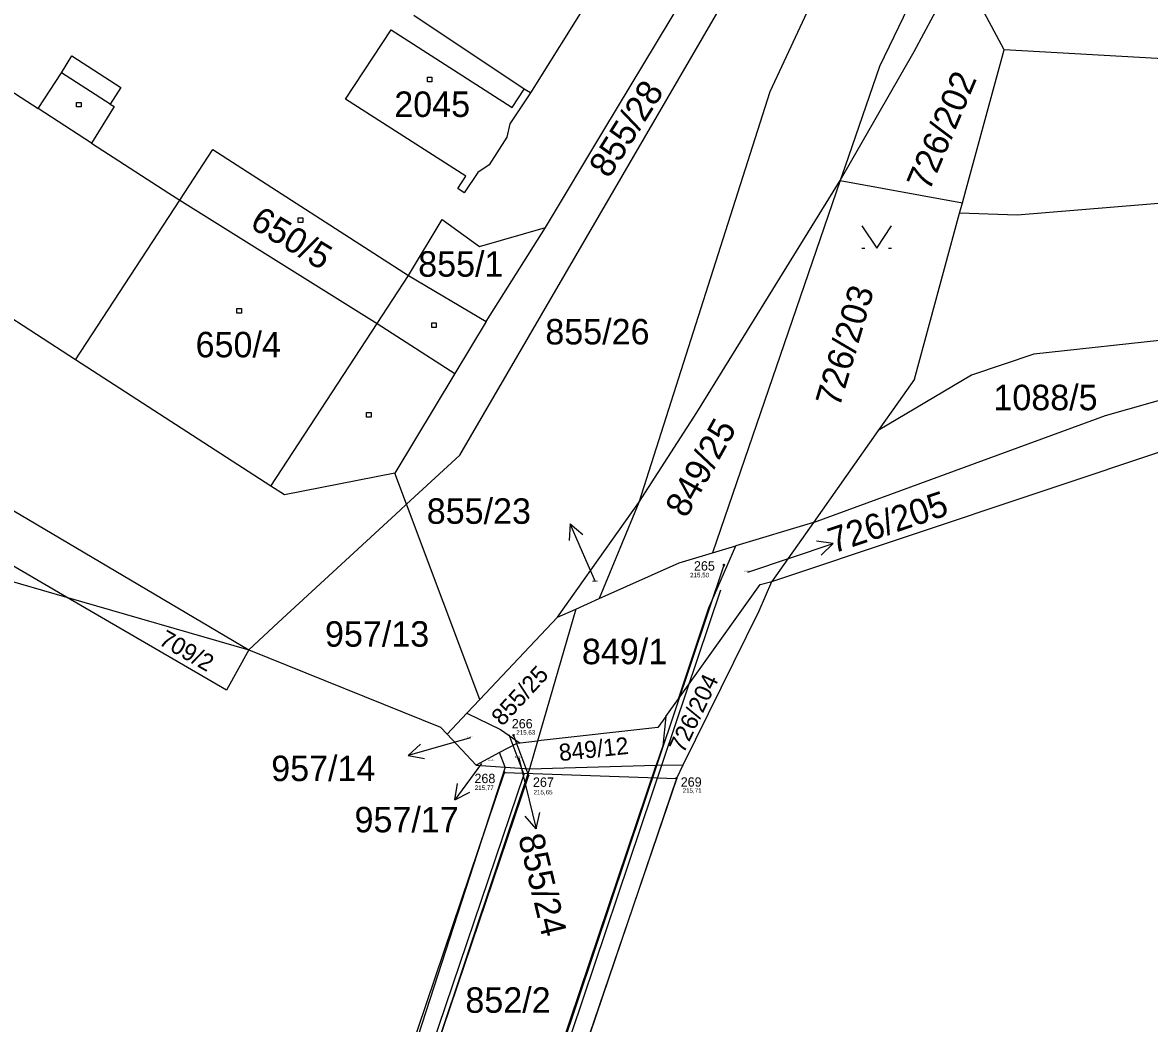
# Model space of a CAD drawing. Extents: x -711879 to -711361, y -1048782 to -1048177.
# Drawn here: x -711646.6 to -711571.3, y -1048438.5 to -1048371.7 of the extents above; entities that cross this region are included whole.
import ezdxf

# ---------------------------------------------------------------- set-up
doc = ezdxf.new("R2010")
doc.units = 0
for name, color, linetype in [('body', 7, 'Continuous'), ('kresba', 7, 'Continuous'), ('Vrstva 1', 7, 'Continuous'), ('Vrstva 13', 7, 'Continuous'), ('Vrstva 14', 7, 'Continuous'), ('Vrstva 15', 7, 'Continuous'), ('Vrstva 16', 7, 'Continuous'), ('Vrstva 2', 7, 'Continuous'), ('Vrstva 20', 7, 'Continuous'), ('Vrstva 23', 7, 'Continuous'), ('Vrstva 25', 7, 'Continuous'), ('Vrstva 41', 7, 'Continuous'), ('Vrstva 46', 7, 'Continuous'), ('výšky', 7, 'Continuous')]:
    doc.layers.add(name, color=color, linetype=linetype)

msp = doc.modelspace()

# ---------------------------------------------------------------- linework, layer by layer
at = {"layer": 'kresba'}
msp.add_line((-711599.74, -1048407.86), (-711614.77, -1048452.56), dxfattribs=at)
for points in [[(-711630.48, -1048500.11), (-711629, -1048495.83), (-711614.47, -1048452.67), (-711599.94, -1048409.51)], [(-711614.09, -1048419.16), (-711613.1, -1048421.84), (-711622.61, -1048449.96)], [(-711613.78, -1048419.23), (-711612.79, -1048421.91), (-711622.3, -1048450.03)]]:
    msp.add_lwpolyline(points, dxfattribs=at)
msp.add_lwpolyline([(-711614.39, -1048421.71), (-711602.91, -1048422.1), (-711612.41, -1048450.08), (-711623.65, -1048449.1)], close=True, dxfattribs=at)
at = {"layer": 'Vrstva 1'}
for p, q in [((-711598.7, -1048354.08), (-711612.66, -1048376.35)), ((-711607.76, -1048378.85), (-711593.27, -1048354.78)), ((-711678.36, -1048356.19), (-711645.51, -1048377.4)), ((-711590.17, -1048362.3), (-711596.67, -1048376.28)), ((-711583.43, -1048362.34), (-711589.37, -1048374.59)), ((-711617.37, -1048400.54), (-711595.83, -1048363.49)), ((-711643.01, -1048394.17), (-711685.27, -1048366.88)), ((-711587.04, -1048373.59), (-711584.04, -1048367.95)), ((-711613.07, -1048376.1), (-711620.44, -1048371.18)), ((-711581.05, -1048373.49), (-711582.56, -1048370.66)), ((-711624.99, -1048376.78), (-711621.96, -1048372.14)), ((-711621.96, -1048372.14), (-711613.87, -1048377.34)), ((-711583.58, -1048382.77), (-711581.05, -1048373.49)), ((-711557.26, -1048374.8), (-711581.05, -1048373.49)), ((-711643.94, -1048375.01), (-711643.26, -1048373.89)), ((-711643.26, -1048373.89), (-711639.98, -1048376)), ((-711591.98, -1048382.19), (-711587.04, -1048373.59)), ((-711589.37, -1048374.59), (-711591.65, -1048381.24)), ((-711645.51, -1048377.4), (-711643.94, -1048375.01)), ((-711639.98, -1048376), (-711640.7, -1048377.1)), ((-711612.66, -1048376.35), (-711614.03, -1048378.43)), ((-711613.87, -1048377.34), (-711613.07, -1048376.1)), ((-711612.66, -1048376.35), (-711613.07, -1048376.1)), ((-711596.67, -1048376.28), (-711605.43, -1048403.69)), ((-711640.7, -1048377.1), (-711640.43, -1048377.27)), ((-711616.96, -1048381.91), (-711624.99, -1048376.78)), ((-711640.43, -1048377.27), (-711641.94, -1048379.7)), ((-711614.03, -1048378.43), (-711614.22, -1048379.32)), ((-711502.66, -1048378.02), (-711580.18, -1048384.52)), ((-711614.22, -1048379.32), (-711615.41, -1048381.15)), ((-711611.66, -1048385.34), (-711607.76, -1048378.85)), ((-711641.94, -1048379.7), (-711636.78, -1048383.04)), ((-711636.05, -1048383.51), (-711633.84, -1048380.13)), ((-711633.84, -1048380.13), (-711620.8, -1048388.55)), ((-711616.17, -1048381.67), (-711617.07, -1048383.03)), ((-711615.41, -1048381.15), (-711616.17, -1048381.67)), ((-711591.65, -1048381.24), (-711591.98, -1048382.19)), ((-711617.49, -1048382.73), (-711616.96, -1048381.91)), ((-711601.56, -1048397.68), (-711591.98, -1048382.19)), ((-711591.98, -1048382.19), (-711600.51, -1048407.04)), ((-711591.98, -1048382.19), (-711583.83, -1048383.69)), ((-711636.78, -1048383.04), (-711636.05, -1048383.51)), ((-711617.07, -1048383.03), (-711617.49, -1048382.73)), ((-711583.83, -1048383.69), (-711583.58, -1048382.77)), ((-711643.01, -1048394.17), (-711636.05, -1048383.51)), ((-711636.05, -1048383.51), (-711622.88, -1048391.74)), ((-711584.02, -1048384.39), (-711583.83, -1048383.69)), ((-711587.03, -1048395.45), (-711584.02, -1048384.39)), ((-711580.18, -1048384.52), (-711584.02, -1048384.39)), ((-711620.8, -1048388.55), (-711618.55, -1048384.81)), ((-711618.55, -1048384.81), (-711616.05, -1048386.61)), ((-711616.05, -1048386.61), (-711611.66, -1048385.34)), ((-711615.61, -1048391.61), (-711611.66, -1048385.34)), ((-711620.8, -1048388.55), (-711615.61, -1048391.61)), ((-711548.59, -1048390.49), (-711579.07, -1048393.79)), ((-711574.28, -1048397.89), (-711548.59, -1048390.49)), ((-711596.54, -1048408.95), (-711544.38, -1048391.51)), ((-711622.88, -1048391.74), (-711617.7, -1048395.07)), ((-711615.61, -1048391.61), (-711617.7, -1048395.07)), ((-711579.07, -1048393.79), (-711583.23, -1048395.19)), ((-711629.97, -1048402.59), (-711643.01, -1048394.17)), ((-711617.7, -1048395.07), (-711621.7, -1048401.73)), ((-711583.23, -1048395.19), (-711589.45, -1048398.89)), ((-711587.03, -1048395.45), (-711588.09, -1048396.96)), ((-711588.09, -1048396.96), (-711589.45, -1048398.89)), ((-711605.43, -1048403.69), (-711601.56, -1048397.68)), ((-711593.77, -1048405.02), (-711574.28, -1048397.89)), ((-711589.45, -1048398.89), (-711593.77, -1048405.02)), ((-711620.92, -1048403.81), (-711617.37, -1048400.54)), ((-711653.14, -1048400.7), (-711631.45, -1048413.51)), ((-711621.7, -1048401.73), (-711629.06, -1048403.18)), ((-711620.92, -1048403.81), (-711621.7, -1048401.73)), ((-711629.06, -1048403.18), (-711629.97, -1048402.59)), ((-711664.88, -1048403.87), (-711643.62, -1048410)), ((-711629.49, -1048411.7), (-711621.36, -1048404.21)), ((-711621.36, -1048404.21), (-711620.92, -1048403.81)), ((-711616.04, -1048416.84), (-711620.92, -1048403.81)), ((-711610.85, -1048411.35), (-711605.43, -1048403.69)), ((-711605.43, -1048403.69), (-711608.06, -1048410.1)), ((-711643.62, -1048410), (-711653.11, -1048404.49)), ((-711593.77, -1048405.02), (-711598.96, -1048406.58)), ((-711593.77, -1048405.02), (-711596.54, -1048408.95)), ((-711600.51, -1048407.04), (-711598.96, -1048406.58)), ((-711602.74, -1048407.71), (-711600.51, -1048407.04)), ((-711608.06, -1048410.1), (-711602.74, -1048407.71)), ((-711602.78, -1048416.79), (-711597.32, -1048409.17)), ((-711597.39, -1048410.92), (-711596.54, -1048408.95)), ((-711597.32, -1048409.17), (-711596.54, -1048408.95)), ((-711643.62, -1048410), (-711631.45, -1048413.51)), ((-711632.93, -1048416.21), (-711643.62, -1048410)), ((-711609.62, -1048410.8), (-711608.06, -1048410.1)), ((-711609.62, -1048410.8), (-711612.18, -1048419.61)), ((-711610.85, -1048411.35), (-711609.62, -1048410.8)), ((-711602.46, -1048421.2), (-711597.39, -1048410.92)), ((-711629.49, -1048411.7), (-711631.45, -1048413.51)), ((-711616.04, -1048416.84), (-711610.85, -1048411.35)), ((-711631.45, -1048413.51), (-711632.93, -1048416.21)), ((-711631.45, -1048413.51), (-711618.65, -1048418.68)), ((-711616.9, -1048417.75), (-711616.04, -1048416.84)), ((-711603.62, -1048417.96), (-711602.78, -1048416.79)), ((-711618.22, -1048419.15), (-711616.9, -1048417.75)), ((-711603.62, -1048417.96), (-711604.15, -1048418.71)), ((-711603.62, -1048417.96), (-711603.83, -1048419.93)), ((-711618.65, -1048418.68), (-711618.22, -1048419.15)), ((-711618.22, -1048419.15), (-711616.27, -1048421.22)), ((-711604.15, -1048418.71), (-711611.95, -1048419.58)), ((-711613.57, -1048419.77), (-711614.71, -1048420.38)), ((-711613.34, -1048419.74), (-711613.57, -1048419.77)), ((-711612.18, -1048419.61), (-711613.34, -1048419.74)), ((-711612.18, -1048419.61), (-711612.72, -1048421.45)), ((-711611.95, -1048419.58), (-711612.18, -1048419.61)), ((-711603.83, -1048419.93), (-711604.27, -1048421.22)), ((-711614.71, -1048420.38), (-711616.27, -1048421.22)), ((-711614.35, -1048421.34), (-711614.71, -1048420.38)), ((-711614.35, -1048421.34), (-711623.23, -1048448.72)), ((-711616.27, -1048421.22), (-711614.35, -1048421.34)), ((-711614.35, -1048421.34), (-711612.72, -1048421.45)), ((-711612.72, -1048421.45), (-711604.27, -1048421.22)), ((-711604.27, -1048421.22), (-711602.46, -1048421.2)), ((-711602.89, -1048422.08), (-711602.46, -1048421.2)), ((-711602.89, -1048422.08), (-711615.16, -1048458.11))]:
    msp.add_line(p, q, dxfattribs=at)
for points in [[(-711602.78, -1048416.79), (-711600.74, -1048410.71), (-711598.96, -1048406.58)], [(-711616.9, -1048417.75), (-711614.65, -1048418.83), (-711613.34, -1048419.74)]]:
    msp.add_lwpolyline(points, dxfattribs=at)
at = {"layer": 'Vrstva 13'}
for p, q in [((-711608.31, -1048408.99), (-711608.81, -1048407.86)), ((-711598.14, -1048408.33), (-711595.3, -1048407.37)), ((-711616.65, -1048419.39), (-711617.93, -1048419.75)), ((-711613.44, -1048420.73), (-711612.99, -1048422.55))]:
    msp.add_line(p, q, dxfattribs=at)
at = {"layer": 'Vrstva 16'}
for p, q in [((-711610.013, -1048405.112), (-711610.07, -1048406.228)), ((-711608.81, -1048407.86), (-711610.013, -1048405.112)), ((-711610.013, -1048405.112), (-711609.154, -1048405.827)), ((-711595.3, -1048407.37), (-711592.456, -1048406.413)), ((-711592.456, -1048406.413), (-711593.563, -1048406.258)), ((-711592.456, -1048406.413), (-711593.244, -1048407.206)), ((-711617.93, -1048419.75), (-711620.814, -1048420.575)), ((-711620.814, -1048420.575), (-711619.99, -1048419.819)), ((-711620.814, -1048420.575), (-711619.715, -1048420.78)), ((-711615.931, -1048421.113), (-711617.703, -1048423.533)), ((-711617.703, -1048423.533), (-711617.516, -1048422.431)), ((-711617.703, -1048423.533), (-711616.709, -1048423.022)), ((-711612.99, -1048422.55), (-711612.275, -1048425.463)), ((-711612.275, -1048425.463), (-711612.999, -1048424.611)), ((-711612.275, -1048425.463), (-711612.028, -1048424.373))]:
    msp.add_line(p, q, dxfattribs=at)
at = {"layer": 'Vrstva 2'}
for p, q in [((-711640.7, -1048377.1), (-711643.94, -1048375.01)), ((-711641.94, -1048379.7), (-711645.51, -1048377.4)), ((-711622.88, -1048391.74), (-711620.8, -1048388.55)), ((-711629.97, -1048402.59), (-711622.88, -1048391.74)), ((-711612.72, -1048421.45), (-711623.93, -1048454.98)), ((-711613.71, -1048449.23), (-711604.27, -1048421.22))]:
    msp.add_line(p, q, dxfattribs=at)
at = {"layer": 'Vrstva 20'}
for p, q in [((-711599.74, -1048407.86), (-711599.79, -1048407.81)), ((-711599.74, -1048407.86), (-711599.79, -1048407.91)), ((-711599.74, -1048407.86), (-711599.69, -1048407.81)), ((-711599.74, -1048407.86), (-711599.69, -1048407.91)), ((-711613.78, -1048419.23), (-711613.83, -1048419.18)), ((-711613.78, -1048419.23), (-711613.83, -1048419.28)), ((-711613.78, -1048419.23), (-711613.73, -1048419.18)), ((-711613.78, -1048419.23), (-711613.73, -1048419.28)), ((-711614.39, -1048421.71), (-711614.44, -1048421.66)), ((-711614.39, -1048421.71), (-711614.44, -1048421.76)), ((-711614.39, -1048421.71), (-711614.34, -1048421.66)), ((-711614.39, -1048421.71), (-711614.34, -1048421.76)), ((-711612.79, -1048421.91), (-711612.84, -1048421.86)), ((-711612.79, -1048421.91), (-711612.84, -1048421.96)), ((-711612.79, -1048421.91), (-711612.74, -1048421.86)), ((-711612.79, -1048421.91), (-711612.74, -1048421.96)), ((-711602.91, -1048422.1), (-711602.96, -1048422.05)), ((-711602.91, -1048422.1), (-711602.96, -1048422.15)), ((-711602.91, -1048422.1), (-711602.86, -1048422.05)), ((-711602.91, -1048422.1), (-711602.86, -1048422.15))]:
    msp.add_line(p, q, dxfattribs=at)
at = {"layer": 'Vrstva 23'}
for p, q in [((-711590.55, -1048385.22), (-711589.55, -1048386.72)), ((-711589.55, -1048386.72), (-711588.55, -1048385.22)), ((-711590.55, -1048386.72), (-711590.35, -1048386.72)), ((-711588.75, -1048386.72), (-711588.55, -1048386.72))]:
    msp.add_line(p, q, dxfattribs=at)
at = {"layer": 'Vrstva 25'}
for p, q in [((-711619.53, -1048375.31), (-711619.23, -1048375.31)), ((-711619.53, -1048375.61), (-711619.53, -1048375.31)), ((-711619.23, -1048375.61), (-711619.53, -1048375.61)), ((-711619.23, -1048375.31), (-711619.23, -1048375.61)), ((-711642.94, -1048376.99), (-711642.64, -1048376.99)), ((-711642.94, -1048377.29), (-711642.94, -1048376.99)), ((-711642.64, -1048376.99), (-711642.64, -1048377.29)), ((-711642.64, -1048377.29), (-711642.94, -1048377.29)), ((-711628.15, -1048384.7), (-711627.85, -1048384.7)), ((-711628.15, -1048385), (-711628.15, -1048384.7)), ((-711627.85, -1048384.7), (-711627.85, -1048385)), ((-711627.85, -1048385), (-711628.15, -1048385)), ((-711632.24, -1048390.75), (-711631.94, -1048390.75)), ((-711632.24, -1048391.05), (-711632.24, -1048390.75)), ((-711631.94, -1048390.75), (-711631.94, -1048391.05)), ((-711631.94, -1048391.05), (-711632.24, -1048391.05)), ((-711619.24, -1048391.7), (-711618.94, -1048391.7)), ((-711619.24, -1048392), (-711619.24, -1048391.7)), ((-711618.94, -1048392), (-711619.24, -1048392)), ((-711618.94, -1048391.7), (-711618.94, -1048392)), ((-711623.59, -1048397.69), (-711623.29, -1048397.69)), ((-711623.59, -1048397.99), (-711623.59, -1048397.69)), ((-711623.29, -1048397.99), (-711623.59, -1048397.99)), ((-711623.29, -1048397.69), (-711623.29, -1048397.99))]:
    msp.add_line(p, q, dxfattribs=at)
at = {"layer": 'Vrstva 41'}
for p, q in [((-711599.74, -1048407.86), (-711599.74, -1048407.86)), ((-711613.78, -1048419.23), (-711613.78, -1048419.23)), ((-711614.39, -1048421.71), (-711614.39, -1048421.71)), ((-711612.79, -1048421.91), (-711612.79, -1048421.91)), ((-711602.91, -1048422.1), (-711602.91, -1048422.1))]:
    msp.add_line(p, q, dxfattribs=at)
at = {"layer": 'Vrstva 46'}
for p, q in [((-711643.94, -1048375.01), (-711643.94, -1048375.01)), ((-711613.07, -1048376.1), (-711613.07, -1048376.1)), ((-711612.66, -1048376.35), (-711612.66, -1048376.35)), ((-711645.51, -1048377.4), (-711645.51, -1048377.4)), ((-711614.03, -1048378.43), (-711614.03, -1048378.43)), ((-711607.76, -1048378.85), (-711607.76, -1048378.85)), ((-711633.84, -1048380.13), (-711633.84, -1048380.13)), ((-711636.78, -1048383.04), (-711636.78, -1048383.04)), ((-711618.55, -1048384.81), (-711618.55, -1048384.81)), ((-711611.66, -1048385.34), (-711611.66, -1048385.34)), ((-711616.05, -1048386.61), (-711616.05, -1048386.61)), ((-711620.8, -1048388.55), (-711620.8, -1048388.55)), ((-711622.88, -1048391.74), (-711622.88, -1048391.74)), ((-711615.61, -1048391.61), (-711615.61, -1048391.61)), ((-711643.01, -1048394.17), (-711643.01, -1048394.17)), ((-711617.7, -1048395.07), (-711617.7, -1048395.07)), ((-711621.7, -1048401.73), (-711621.7, -1048401.73)), ((-711629.97, -1048402.59), (-711629.97, -1048402.59)), ((-711629.06, -1048403.18), (-711629.06, -1048403.18)), ((-711598.96, -1048406.58), (-711598.96, -1048406.58)), ((-711597.32, -1048409.17), (-711597.32, -1048409.17)), ((-711643.62, -1048410), (-711643.62, -1048410)), ((-711609.62, -1048410.8), (-711609.62, -1048410.8)), ((-711631.45, -1048413.51), (-711631.45, -1048413.51)), ((-711627.56, -1048415.08), (-711627.56, -1048415.08)), ((-711602.78, -1048416.79), (-711602.78, -1048416.79)), ((-711618.22, -1048419.15), (-711618.22, -1048419.15)), ((-711613.34, -1048419.74), (-711613.34, -1048419.74)), ((-711612.18, -1048419.61), (-711612.18, -1048419.61)), ((-711603.83, -1048419.93), (-711603.83, -1048419.93)), ((-711616.27, -1048421.22), (-711616.27, -1048421.22)), ((-711602.98, -1048422.35), (-711602.98, -1048422.35)), ((-711603.18, -1048422.94), (-711603.18, -1048422.94))]:
    msp.add_line(p, q, dxfattribs=at)

# ---------------------------------------------------------------- texts
at = {"layer": 'body'}
for s, p in [('265', (-711601.744, -1048408.231)), ('266', (-711613.901, -1048418.76)), ('268', (-711616.392, -1048422.414)), ('267', (-711612.488, -1048422.663)), ('269', (-711602.625, -1048422.652))]:
    msp.add_text(s, height=0.625, dxfattribs=at).set_placement(p)
at = {"layer": 'Vrstva 14'}
for s, height, rotation, p in [('726/202', 1.7, 67.10949, (-711586.04, -1048382.97)), ('855/28', 1.7, 57.72042, (-711607.416, -1048382.123)), ('726/203', 1.7, 73.5912, (-711592.032, -1048397.4)), ('849/25', 1.7, 60.67656, (-711602.267, -1048404.798)), ('709/2', 1.14, 330.25509, (-711637.528, -1048413.123)), ('855/25', 1.14, 47.28051, (-711614.535, -1048418.667)), ('726/204', 1.14, 64.66392, (-711602.428, -1048420.477)), ('849/12', 1.14, 6.0858, (-711610.693, -1048420.952))]:
    msp.add_text(s, height=height, rotation=rotation, dxfattribs=at).set_placement(p)
for s, height, p in [('855/1', 1.7, (-711620.146, -1048388.62)), ('855/26', 1.7, (-711611.662, -1048393.14)), ('1088/5', 1.7, (-711581.76, -1048397.53)), ('726/205', 0.1, (-711598.437, -1048408.33)), ('855/23', 0.1, (-711608.561, -1048408.99)), ('957/13', 1.7, (-711626.366, -1048413.31)), ('849/1', 1.7, (-711609.219, -1048414.48)), ('957/14', 0.1, (-711616.889, -1048419.39)), ('957/17', 0.1, (-711615.473, -1048420.94)), ('855/24', 0.1, (-711613.69, -1048420.73)), ('852/2', 1.7, (-711616.996, -1048437.74))]:
    msp.add_text(s, height=height, dxfattribs=at).set_placement(p)
at = {"layer": 'Vrstva 15'}
for s, p in [('2045', (-711621.74, -1048377.96)), ('650/4', (-711635, -1048394))]:
    msp.add_text(s, height=1.7, dxfattribs=at).set_placement(p)
msp.add_text('650/5', height=1.7, rotation=329.0184, dxfattribs=at).set_placement((-711631.46, -1048385.3))
at = {"layer": 'Vrstva 16'}
for s, p in [('855/23', (-711619.575, -1048405.11)), ('957/14', (-711629.954, -1048422.28)), ('957/17', (-711624.394, -1048425.698))]:
    msp.add_text(s, height=1.7, dxfattribs=at).set_placement(p)
for s, rotation, p in [('726/205', 18.54954, (-711592.439, -1048407.097)), ('855/24', 283.50639, (-711613.482, -1048426.007))]:
    msp.add_text(s, height=1.7, rotation=rotation, dxfattribs=at).set_placement(p)
at = {"layer": 'výšky'}
for s, p in [('215,50', (-711602, -1048408.68)), ('215,63', (-711613.6, -1048419.18)), ('215,77', (-711616.37, -1048422.87)), ('215,65', (-711612.45, -1048423.17)), ('215,71', (-711602.5, -1048423.06))]:
    msp.add_text(s, height=0.3, dxfattribs=at).set_placement(p)

doc.saveas('drawing.dxf')
